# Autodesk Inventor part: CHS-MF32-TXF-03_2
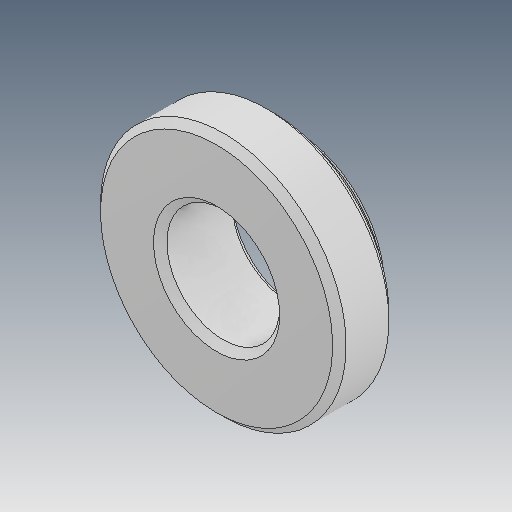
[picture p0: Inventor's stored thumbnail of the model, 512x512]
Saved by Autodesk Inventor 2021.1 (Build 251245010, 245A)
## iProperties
Created: 2021-05
Part Number: CHS-MF32-TXF-03_2
Material: Ogólny
Document SubType Name: Modeling
Designer: user
Density: 1 g/cm^3
Appearance: Domyślna
Author: user
Revision Number: ÈÎºÎ
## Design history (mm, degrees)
feature "ÊäÈë1"
node "Bryła1"
